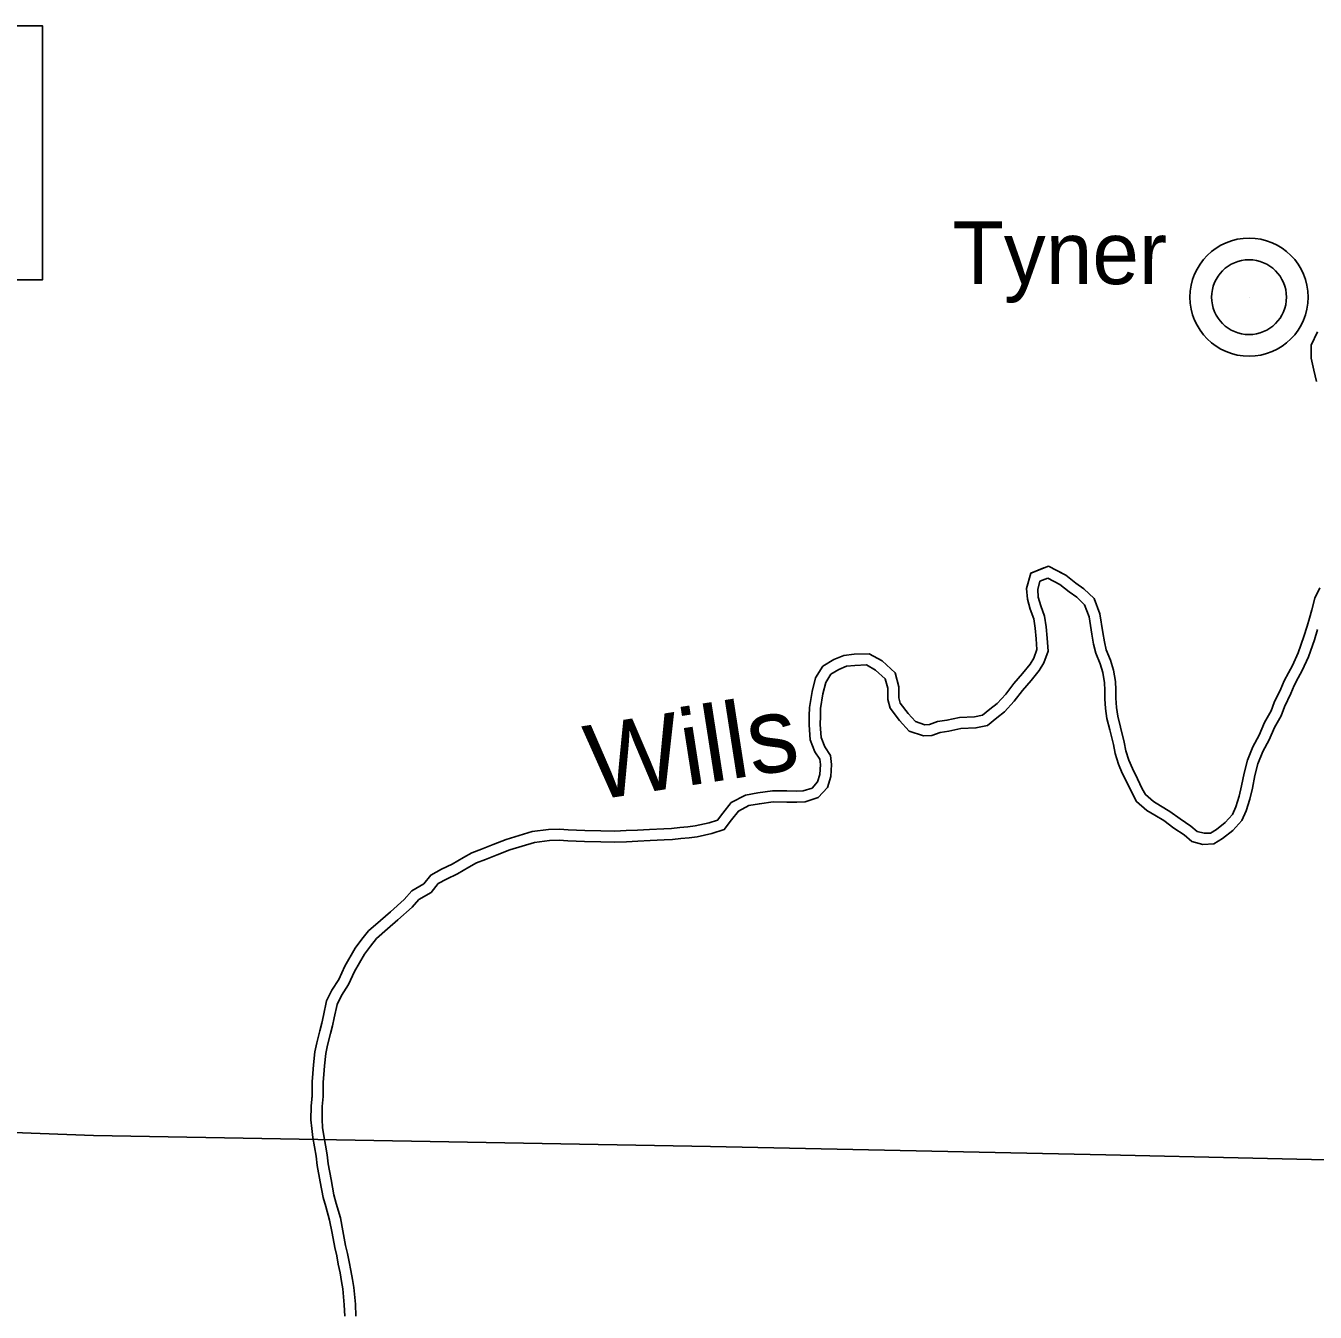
# Model space of a CAD drawing. Extents: x -12.1 to 34, y 0 to 22.
# Drawn here: x -7.59 to -6.067, y 14.162 to 15.682 of the extents above; entities that cross this region are included whole.
import ezdxf

# ---------------------------------------------------------------- set-up
doc = ezdxf.new("R2010")
doc.units = 0
for name, color, linetype in [('BR_P_Gen_Text', 7, 'Continuous'), ('GM_X_Major_River', 7, 'Continuous'), ('GM_X_Major_River_Text', 7, 'Continuous'), ('GM_X_Township', 7, 'Continuous'), ('GM_X_Unincorporated', 7, 'Continuous'), ('GM_X_Unincorporated_Location', 7, 'Continuous'), ('GM_X_Unincorporated_Text', 7, 'Continuous')]:
    doc.layers.add(name, color=color, linetype=linetype)

msp = doc.modelspace()

# ---------------------------------------------------------------- linework, layer by layer
at = {"layer": 'BR_P_Gen_Text'}
msp.add_lwpolyline([(-9.1421, 15.682), (-7.5704, 15.682), (-7.5704, 15.3818), (-9.1421, 15.3818)], close=True, dxfattribs=at)
at = {"layer": 'GM_X_Major_River'}
for points in [[(-6.0659, 15.2617), (-6.0692, 15.2751), (-6.0721, 15.2894), (-6.0722, 15.3046), (-6.0648, 15.3203)], [(-6.0648, 15.3203), (-6.0722, 15.3046), (-6.0721, 15.2894), (-6.0692, 15.2751), (-6.0659, 15.2617)], [(-6.3825, 15.0437), (-6.4032, 15.0355), (-6.4084, 15.0174), (-6.4074, 15.0045), (-6.404, 14.9926), (-6.3999, 14.9812), (-6.398, 14.9704), (-6.3969, 14.9578), (-6.3962, 14.945), (-6.3998, 14.9351), (-6.4042, 14.9277), (-6.413, 14.9168), (-6.4233, 14.9049), (-6.433, 14.8925), (-6.4432, 14.8812), (-6.4516, 14.8746), (-6.4602, 14.8676), (-6.4699, 14.8655), (-6.4875, 14.8647), (-6.5023, 14.8616), (-6.5135, 14.86), (-6.5228, 14.8566), (-6.5283, 14.8563), (-6.5395, 14.8601), (-6.5482, 14.8695), (-6.5574, 14.8818), (-6.5592, 14.8881), (-6.5593, 14.9011), (-6.5636, 14.9174), (-6.5789, 14.9316), (-6.5941, 14.9401), (-6.6121, 14.9395), (-6.6242, 14.9381), (-6.6361, 14.9334), (-6.6489, 14.9254), (-6.6575, 14.9115), (-6.6616, 14.8954), (-6.6645, 14.8766), (-6.6649, 14.8669), (-6.6652, 14.8562), (-6.6638, 14.8383), (-6.6583, 14.8242), (-6.6525, 14.8155), (-6.6518, 14.8091), (-6.6526, 14.7975), (-6.6551, 14.7889), (-6.6617, 14.7815), (-6.6723, 14.7781), (-6.68, 14.7777), (-6.6913, 14.778), (-6.7083, 14.7783), (-6.7258, 14.7758), (-6.7404, 14.7732), (-6.7571, 14.7645), (-6.7669, 14.7519), (-6.7732, 14.7436), (-6.7832, 14.7403), (-6.7995, 14.7369), (-6.8083, 14.7355), (-6.8179, 14.7348), (-6.8276, 14.7337), (-6.8368, 14.7333), (-6.8535, 14.7324), (-6.8679, 14.7316), (-6.8812, 14.7312), (-6.8947, 14.7307), (-6.9109, 14.731), (-6.93, 14.7315), (-6.9496, 14.7321), (-6.9598, 14.7327), (-6.9727, 14.7326), (-6.9923, 14.7301), (-7.0229, 14.7206), (-7.0381, 14.7146), (-7.0518, 14.7092), (-7.0632, 14.7049), (-7.0734, 14.6994), (-7.0865, 14.6917), (-7.0993, 14.6856), (-7.1119, 14.6787), (-7.1201, 14.6683), (-7.1343, 14.6602), (-7.1432, 14.6498), (-7.1595, 14.6354), (-7.1714, 14.6251), (-7.1854, 14.6128), (-7.1932, 14.6028), (-7.2012, 14.5924), (-7.2134, 14.5709), (-7.2206, 14.5554), (-7.2286, 14.5427), (-7.2349, 14.53), (-7.2386, 14.5128), (-7.2407, 14.5038), (-7.243, 14.4947), (-7.2466, 14.4805), (-7.2488, 14.4699), (-7.2502, 14.4543), (-7.2512, 14.4442), (-7.2519, 14.4344), (-7.2521, 14.4178)], [(-6.0622, 15.0181), (-6.068, 15.0057), (-6.0714, 14.992), (-6.0741, 14.9822), (-6.0771, 14.9728), (-6.0809, 14.9604), (-6.0876, 14.9413), (-6.0945, 14.9263), (-6.0992, 14.9176), (-6.1041, 14.908), (-6.108, 14.8986), (-6.1158, 14.8824), (-6.1194, 14.8725), (-6.1273, 14.8589), (-6.1337, 14.844), (-6.1411, 14.8301), (-6.1476, 14.8143), (-6.1514, 14.7992), (-6.1545, 14.7842), (-6.1574, 14.7717), (-6.1612, 14.7593), (-6.1653, 14.7501), (-6.1737, 14.7407), (-6.1842, 14.7326), (-6.1912, 14.7283), (-6.1986, 14.728), (-6.207, 14.7302), (-6.2143, 14.7366), (-6.2271, 14.7449), (-6.239, 14.7538), (-6.25, 14.7605), (-6.2586, 14.7656), (-6.268, 14.7738), (-6.2718, 14.7806), (-6.2774, 14.7924), (-6.2833, 14.8045), (-6.2874, 14.8143), (-6.2912, 14.8254), (-6.293, 14.8355), (-6.2975, 14.8533), (-6.3006, 14.8662), (-6.3023, 14.8768), (-6.303, 14.8875), (-6.3031, 14.8973), (-6.3035, 14.9072), (-6.3056, 14.9209), (-6.3093, 14.9326), (-6.3142, 14.9449), (-6.3164, 14.9541), (-6.3182, 14.9654), (-6.3217, 14.9873), (-6.3287, 15.0055), (-6.3408, 15.017), (-6.3501, 15.0236), (-6.3619, 15.033), (-6.3825, 15.0437)], [(-7.2521, 14.4174), (-7.2519, 14.4344), (-7.2512, 14.4442), (-7.2502, 14.4543), (-7.2488, 14.4699), (-7.2466, 14.4805), (-7.243, 14.4947), (-7.2407, 14.5038), (-7.2386, 14.5128), (-7.2349, 14.53), (-7.2286, 14.5427), (-7.2206, 14.5554), (-7.2134, 14.5709), (-7.2012, 14.5924), (-7.1932, 14.6028), (-7.1854, 14.6128), (-7.1714, 14.6251), (-7.1595, 14.6354), (-7.1432, 14.6498), (-7.1343, 14.6602), (-7.1201, 14.6683), (-7.1119, 14.6787), (-7.0993, 14.6856), (-7.0865, 14.6917), (-7.0734, 14.6994), (-7.0632, 14.7049), (-7.0518, 14.7092), (-7.0381, 14.7146), (-7.0229, 14.7206), (-6.9923, 14.7301), (-6.9727, 14.7326), (-6.9598, 14.7327), (-6.9496, 14.7321), (-6.93, 14.7315), (-6.9109, 14.731), (-6.8947, 14.7307), (-6.8812, 14.7312), (-6.8679, 14.7316), (-6.8535, 14.7324), (-6.8368, 14.7333), (-6.8276, 14.7337), (-6.8179, 14.7348), (-6.8083, 14.7355), (-6.7995, 14.7369), (-6.7832, 14.7403), (-6.7732, 14.7436), (-6.7669, 14.7519), (-6.7571, 14.7645), (-6.7404, 14.7732), (-6.7258, 14.7758), (-6.7083, 14.7783), (-6.6913, 14.778), (-6.68, 14.7777), (-6.6723, 14.7781), (-6.6617, 14.7815), (-6.6551, 14.7889), (-6.6526, 14.7975), (-6.6518, 14.8091), (-6.6525, 14.8155), (-6.6583, 14.8242), (-6.6638, 14.8383), (-6.6652, 14.8562), (-6.6649, 14.8669), (-6.6645, 14.8766), (-6.6616, 14.8954), (-6.6575, 14.9115), (-6.6489, 14.9254), (-6.6361, 14.9334), (-6.6242, 14.9381), (-6.6121, 14.9395), (-6.5941, 14.9401), (-6.5789, 14.9316), (-6.5636, 14.9174), (-6.5593, 14.9011), (-6.5592, 14.8881), (-6.5574, 14.8818), (-6.5482, 14.8695), (-6.5395, 14.8601), (-6.5283, 14.8563), (-6.5228, 14.8566), (-6.5135, 14.86), (-6.5023, 14.8616), (-6.4875, 14.8647), (-6.4699, 14.8655), (-6.4602, 14.8676), (-6.4516, 14.8746), (-6.4432, 14.8812), (-6.433, 14.8925), (-6.4233, 14.9049), (-6.413, 14.9168), (-6.4042, 14.9277), (-6.3998, 14.9351), (-6.3962, 14.945), (-6.3969, 14.9578), (-6.398, 14.9704), (-6.3999, 14.9812), (-6.404, 14.9926), (-6.4074, 15.0045), (-6.4084, 15.0174), (-6.4032, 15.0355), (-6.388, 15.0415)], [(-7.2391, 14.4172), (-7.2388, 14.4339), (-7.2382, 14.4431), (-7.2372, 14.4531), (-7.2359, 14.468), (-7.2338, 14.4776), (-7.2304, 14.4915), (-7.228, 14.5007), (-7.2259, 14.51), (-7.2225, 14.5256), (-7.2172, 14.5363), (-7.2092, 14.5492), (-7.2018, 14.5649), (-7.1903, 14.5852), (-7.1829, 14.5948), (-7.1759, 14.6038), (-7.1628, 14.6152), (-7.1508, 14.6256), (-7.1339, 14.6406), (-7.1259, 14.6499), (-7.1114, 14.6582), (-7.1033, 14.6686), (-7.0934, 14.674), (-7.0804, 14.6801), (-7.0669, 14.688), (-7.0578, 14.6931), (-7.0472, 14.697), (-7.0334, 14.7025), (-7.0185, 14.7083), (-6.9895, 14.7173), (-6.9718, 14.7196), (-6.9601, 14.7197), (-6.9502, 14.719), (-6.9304, 14.7185), (-6.9112, 14.7179), (-6.8946, 14.7177), (-6.8808, 14.7181), (-6.8673, 14.7186), (-6.8528, 14.7194), (-6.8361, 14.7202), (-6.8266, 14.7206), (-6.8167, 14.7218), (-6.8067, 14.7226), (-6.7972, 14.724), (-6.7799, 14.7277), (-6.7654, 14.7324), (-6.7566, 14.7439), (-6.7485, 14.7542), (-6.7361, 14.7607), (-6.7237, 14.7629), (-6.7075, 14.7652), (-6.6915, 14.7649), (-6.6798, 14.7647), (-6.6699, 14.7651), (-6.6544, 14.7702), (-6.6434, 14.7823), (-6.6396, 14.7952), (-6.6387, 14.8094), (-6.6398, 14.82), (-6.6466, 14.8303), (-6.6509, 14.8413), (-6.6521, 14.8565), (-6.6518, 14.8665), (-6.6515, 14.8754), (-6.6488, 14.8928), (-6.6453, 14.9063), (-6.6394, 14.9159), (-6.6302, 14.9217), (-6.621, 14.9253), (-6.6111, 14.9264), (-6.5973, 14.9269), (-6.5866, 14.9209), (-6.5752, 14.9104), (-6.5723, 14.8994), (-6.5722, 14.8862), (-6.5693, 14.876), (-6.5582, 14.8611), (-6.5468, 14.8488), (-6.5301, 14.8432), (-6.5202, 14.8436), (-6.5103, 14.8472), (-6.5, 14.8487), (-6.4859, 14.8517), (-6.4682, 14.8525), (-6.4544, 14.8555), (-6.4435, 14.8644), (-6.4343, 14.8716), (-6.423, 14.8841), (-6.4132, 14.8966), (-6.403, 14.9084), (-6.3935, 14.9202), (-6.3879, 14.9295), (-6.383, 14.943), (-6.3839, 14.9587), (-6.385, 14.9721), (-6.3872, 14.9846), (-6.3915, 14.9966), (-6.3945, 15.0069), (-6.3952, 15.0161), (-6.3925, 15.0257), (-6.3833, 15.0293)], [(-6.3833, 15.0293), (-6.369, 15.022), (-6.358, 15.0132), (-6.3491, 15.0069), (-6.3398, 14.9981), (-6.3344, 14.9839), (-6.3311, 14.9633), (-6.3292, 14.9516), (-6.3267, 14.941), (-6.3216, 14.9282), (-6.3184, 14.9179), (-6.3165, 14.9059), (-6.3161, 14.897), (-6.3161, 14.887), (-6.3153, 14.8753), (-6.3134, 14.8636), (-6.3101, 14.8501), (-6.3058, 14.8328), (-6.3039, 14.8221), (-6.2996, 14.8097), (-6.2953, 14.7991), (-6.2892, 14.7867), (-6.2834, 14.7747), (-6.2784, 14.7655), (-6.2663, 14.7549), (-6.2567, 14.7493), (-6.2463, 14.743), (-6.2346, 14.7342), (-6.2221, 14.7261), (-6.2132, 14.7184), (-6.2001, 14.7149), (-6.1873, 14.7154), (-6.1768, 14.7218), (-6.1648, 14.7312), (-6.1542, 14.743), (-6.149, 14.7547), (-6.1448, 14.7682), (-6.1417, 14.7814), (-6.1386, 14.7964), (-6.1352, 14.8102), (-6.1293, 14.8245), (-6.1219, 14.8384), (-6.1156, 14.853), (-6.1076, 14.8669), (-6.1038, 14.8773), (-6.0961, 14.8933), (-6.0922, 14.9026), (-6.0877, 14.9115), (-6.0828, 14.9204), (-6.0755, 14.9364), (-6.0685, 14.9564), (-6.0647, 14.9689)], [(-6.3773, 15.0409), (-6.3619, 15.033), (-6.3501, 15.0236), (-6.3408, 15.017), (-6.3287, 15.0055), (-6.3217, 14.9873), (-6.3182, 14.9654), (-6.3164, 14.9541), (-6.3142, 14.9449), (-6.3093, 14.9326), (-6.3056, 14.9209), (-6.3035, 14.9072), (-6.3031, 14.8973), (-6.303, 14.8875), (-6.3023, 14.8768), (-6.3006, 14.8662), (-6.2975, 14.8533), (-6.293, 14.8355), (-6.2912, 14.8254), (-6.2874, 14.8143), (-6.2833, 14.8045), (-6.2774, 14.7924), (-6.2718, 14.7806), (-6.268, 14.7738), (-6.2586, 14.7656), (-6.25, 14.7605), (-6.239, 14.7538), (-6.2271, 14.7449), (-6.2143, 14.7366), (-6.207, 14.7302), (-6.1986, 14.728), (-6.1912, 14.7283), (-6.1842, 14.7326), (-6.1737, 14.7407), (-6.1653, 14.7501), (-6.1612, 14.7593), (-6.1574, 14.7717), (-6.1545, 14.7842), (-6.1514, 14.7992), (-6.1476, 14.8143), (-6.1411, 14.8301), (-6.1337, 14.844), (-6.1273, 14.8589), (-6.1194, 14.8725), (-6.1158, 14.8824), (-6.108, 14.8986), (-6.1041, 14.908), (-6.0992, 14.9176), (-6.0945, 14.9263), (-6.0876, 14.9413), (-6.0809, 14.9604), (-6.0771, 14.9728), (-6.0741, 14.9822), (-6.0714, 14.992), (-6.068, 15.0057), (-6.0622, 15.0181)], [(-7.2135, 14.1574), (-7.214, 14.1708), (-7.2158, 14.1898), (-7.2172, 14.1986), (-7.219, 14.2089), (-7.2212, 14.2191), (-7.223, 14.2289), (-7.2252, 14.2385), (-7.2285, 14.2557), (-7.2314, 14.2708), (-7.2359, 14.2869), (-7.239, 14.2978), (-7.2424, 14.3164), (-7.2462, 14.3357), (-7.2473, 14.3465), (-7.2491, 14.3575), (-7.251, 14.3686), (-7.2525, 14.3791), (-7.2534, 14.3894), (-7.2531, 14.4057), (-7.2521, 14.4182)], [(-7.2521, 14.4178), (-7.2531, 14.4057), (-7.2534, 14.3894), (-7.2525, 14.3791), (-7.251, 14.3686), (-7.2491, 14.3575), (-7.2473, 14.3465), (-7.2462, 14.3357), (-7.2424, 14.3164), (-7.239, 14.2978), (-7.2359, 14.2869), (-7.2314, 14.2708), (-7.2285, 14.2557), (-7.2252, 14.2385), (-7.223, 14.2289), (-7.2212, 14.2191), (-7.219, 14.2089), (-7.2172, 14.1986), (-7.2158, 14.1898), (-7.214, 14.1708), (-7.2135, 14.1574)], [(-7.2005, 14.1577), (-7.2009, 14.1716), (-7.2028, 14.1915), (-7.2043, 14.2007), (-7.2062, 14.2114), (-7.2084, 14.2216), (-7.2102, 14.2316), (-7.2124, 14.2411), (-7.2157, 14.2582), (-7.2186, 14.2738), (-7.2234, 14.2905), (-7.2263, 14.3007), (-7.2296, 14.3188), (-7.2332, 14.3376), (-7.2344, 14.3483), (-7.2362, 14.3596), (-7.2381, 14.3706), (-7.2396, 14.3806), (-7.2403, 14.3898), (-7.2401, 14.4051), (-7.2391, 14.4172)]]:
    msp.add_lwpolyline(points, dxfattribs=at)
at = {"layer": 'GM_X_Township'}
msp.add_lwpolyline([(-8.927, 13.7314), (-8.914, 14.2676), (-8.9099, 14.4109), (-8.831, 14.4116), (-7.8992, 14.3854), (-7.5102, 14.3711), (-6.7817, 14.358), (-6.3147, 14.3482), (-5.9676, 14.3404), (-5.5555, 14.3272), (-5.5441, 14.3266), (-4.9567, 14.2961), (-4.9556, 14.2962), (-4.9512, 14.2965), (-4.9462, 14.2967), (-4.9388, 14.2969), (-4.932, 14.2968), (-4.9249, 14.2966), (-4.9161, 14.2962), (-4.9092, 14.2959), (-4.9035, 14.2955), (-4.4383, 14.2829)], dxfattribs=at)
at = {"layer": 'GM_X_Unincorporated'}
for radius in [0.0698, 0.0442]:
    msp.add_circle((-6.1456, 15.3614), radius, dxfattribs=at)
at = {"layer": 'GM_X_Unincorporated_Location'}
msp.add_line((-6.1456, 15.3614), (-6.1456, 15.3614), dxfattribs=at)

# ---------------------------------------------------------------- texts
at = {"layer": 'GM_X_Major_River_Text'}
msp.add_text('Wills', height=0.08878, rotation=8.8402, dxfattribs=at).set_placement((-6.9211, 14.7665))
at = {"layer": 'GM_X_Unincorporated_Text'}
msp.add_text('Tyner', height=0.07404, rotation=0, dxfattribs=at).set_placement((-6.4957, 15.3768))

doc.saveas('drawing.dxf')
